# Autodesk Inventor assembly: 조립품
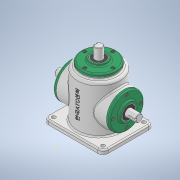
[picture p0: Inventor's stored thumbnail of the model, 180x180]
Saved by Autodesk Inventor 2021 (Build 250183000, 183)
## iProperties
Created: 2021-02
Part Number: 조립품
Document SubType Name: Assembly
Designer: 201-09
Author: 201-09
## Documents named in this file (16)
- C:\Users\201-09\Desktop\시험\조립품.iam
- C:\Users\201-09\Desktop\시험\본체.ipt
- C:\Users\201-09\Desktop\시험\커버.ipt
- C:\Users\201-09\Desktop\시험\베어링 6203.ipt
- C:\Users\201-09\Desktop\시험\오일 실.ipt
- 오일 실.ipt
- C:\Users\201-09\Desktop\시험\메인 축.ipt
- 메인 축.ipt
- C:\Users\201-09\Desktop\시험\키 5x5.ipt
- C:\Users\201-09\Desktop\시험\메인 베벨기어.ipt
- C:\Users\201-09\Desktop\시험\서브 축.ipt
- 서브 축.ipt
- C:\Users\201-09\Desktop\시험\키 4x4.ipt
- C:\Users\201-09\Desktop\시험\서브 베벨기어.ipt
- C:\Users\201-09\Desktop\시험\볼트 M4.ipt
- 볼트 M4.ipt
